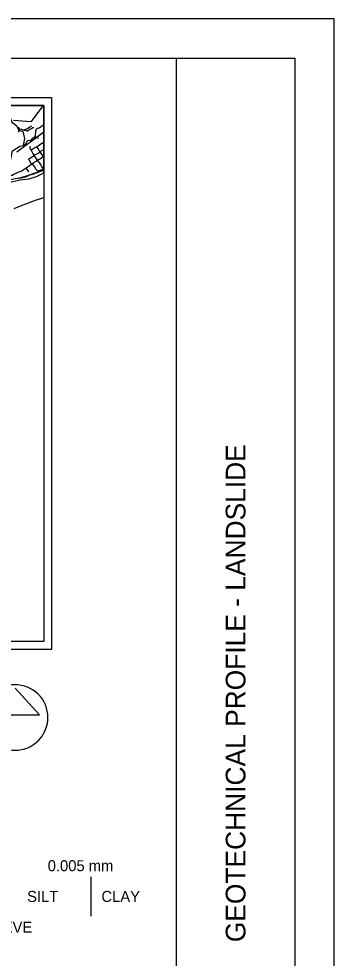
# Model space of a CAD drawing. Extents: x 0 to 34, y 0 to 22.
# Drawn here: x 30 to 34, y 10.08 to 22 of the extents above; entities that cross this region are included whole.
import ezdxf

# ---------------------------------------------------------------- set-up
doc = ezdxf.new("R2010")
doc.units = 0
for name, color, linetype in [('Default', 7, 'Continuous'), ('GM_X_City_Street', 7, 'Continuous'), ('GM_X_County_Road', 7, 'Continuous'), ('GM_X_Major_River', 7, 'Continuous'), ('GM_X_Minor_River', 7, 'Continuous'), ('GM_X_Rail_Line', 7, 'Continuous'), ('GM_X_Section_Text', 7, 'Continuous'), ('GM_X_State_Route', 7, 'Continuous'), ('SH_Border', 7, 'Continuous'), ('SH_Cut_Line', 7, 'Continuous'), ('SH_Data', 7, 'Continuous'), ('SH_Text', 7, 'Continuous')]:
    doc.layers.add(name, color=color, linetype=linetype)

msp = doc.modelspace()

# ---------------------------------------------------------------- linework, layer by layer
at = {"layer": 'Default'}
for points in [[(29.876, 19.923), (30.013, 19.958), (30.128, 19.97), (30.226, 20), (30.317, 20.045), (30.317, 20.9), (27.72, 20.9)], [(29.996, 19.977), (30.019, 19.981), (30.034, 19.983), (30.048, 19.987), (30.071, 19.992), (30.086, 19.995), (30.095, 19.998), (30.108, 20.005), (30.12, 20.011), (30.13, 20.016), (30.147, 20.02), (30.161, 20.025), (30.174, 20.029), (30.193, 20.035), (30.206, 20.04), (30.223, 20.045), (30.239, 20.05), (30.256, 20.057), (30.27, 20.062), (30.283, 20.069), (30.291, 20.072), (30.308, 20.078), (30.317, 20.081), (30.317, 20.9), (29.82, 20.9)], [(29.876, 19.923), (30.013, 19.958), (30.128, 19.97), (30.226, 20), (30.317, 20.045), (30.317, 20.9), (30.309, 20.9), (30.154, 20.693), (29.933, 20.71)]]:
    msp.add_lwpolyline(points, dxfattribs=at)
at = {"layer": 'GM_X_City_Street'}
for points in [[(30.005, 20.606), (30.008, 20.606), (30.01, 20.606), (30.013, 20.606), (30.016, 20.605), (30.032, 20.6), (30.036, 20.599), (30.041, 20.597), (30.046, 20.596), (30.05, 20.595), (30.056, 20.593), (30.07, 20.59), (30.073, 20.589), (30.079, 20.588), (30.096, 20.583), (30.104, 20.581), (30.108, 20.58), (30.111, 20.58), (30.114, 20.58), (30.117, 20.581), (30.119, 20.582), (30.122, 20.583), (30.129, 20.588), (30.134, 20.592), (30.139, 20.596), (30.143, 20.598), (30.156, 20.606), (30.167, 20.613), (30.174, 20.617), (30.179, 20.619), (30.183, 20.621), (30.186, 20.622), (30.188, 20.622), (30.193, 20.622)], [(30.07, 20.59), (30.073, 20.592), (30.074, 20.593), (30.075, 20.594), (30.077, 20.595), (30.08, 20.596), (30.084, 20.597), (30.092, 20.6), (30.099, 20.602), (30.104, 20.605), (30.111, 20.607), (30.116, 20.611), (30.139, 20.625), (30.154, 20.635), (30.159, 20.639), (30.165, 20.642)], [(30.158, 20.333), (30.154, 20.34), (30.151, 20.346), (30.148, 20.352), (30.147, 20.354), (30.146, 20.355), (30.146, 20.356), (30.146, 20.358), (30.145, 20.36), (30.145, 20.362), (30.145, 20.364), (30.145, 20.366), (30.145, 20.369), (30.146, 20.373), (30.147, 20.377), (30.149, 20.385)], [(30.158, 20.333), (30.16, 20.336), (30.162, 20.338), (30.163, 20.339), (30.165, 20.341), (30.17, 20.344), (30.18, 20.351), (30.192, 20.358), (30.218, 20.373), (30.23, 20.38), (30.246, 20.39), (30.264, 20.402), (30.294, 20.421), (30.305, 20.427), (30.309, 20.43), (30.316, 20.435), (30.317, 20.435)], [(30.31, 20.252), (30.305, 20.261), (30.29, 20.286), (30.275, 20.31), (30.272, 20.314), (30.261, 20.331), (30.245, 20.356), (30.239, 20.367), (30.23, 20.38)], [(30.317, 20.408), (30.31, 20.419), (30.305, 20.427)], [(30.13, 20.22), (30.131, 20.222), (30.132, 20.224), (30.133, 20.226), (30.135, 20.228), (30.136, 20.229), (30.138, 20.231), (30.141, 20.233), (30.162, 20.246), (30.17, 20.251), (30.186, 20.261), (30.198, 20.268), (30.222, 20.283), (30.246, 20.297), (30.272, 20.314), (30.285, 20.323), (30.317, 20.342)], [(30.311, 20.099), (30.311, 20.1), (30.311, 20.102), (30.31, 20.103), (30.31, 20.104), (30.308, 20.107), (30.304, 20.114), (30.295, 20.127), (30.276, 20.154), (30.262, 20.175), (30.257, 20.183), (30.251, 20.191), (30.242, 20.202), (30.239, 20.207), (30.235, 20.212), (30.226, 20.224), (30.211, 20.248), (30.198, 20.268), (30.188, 20.284), (30.181, 20.296), (30.161, 20.328), (30.158, 20.333)], [(30.163, 20.157), (30.158, 20.166), (30.136, 20.203), (30.133, 20.207), (30.132, 20.212), (30.131, 20.215), (30.13, 20.217), (30.13, 20.218), (30.13, 20.219), (30.13, 20.22)], [(30.239, 20.07), (30.237, 20.071), (30.236, 20.072), (30.235, 20.073), (30.233, 20.075), (30.223, 20.09), (30.199, 20.126), (30.187, 20.143), (30.178, 20.157), (30.174, 20.164)], [(30.129, 20.058), (30.119, 20.072), (30.112, 20.084), (30.104, 20.095), (30.1, 20.1), (30.095, 20.109)], [(30.239, 20.07), (30.243, 20.07), (30.247, 20.071), (30.255, 20.074), (30.272, 20.08), (30.282, 20.084), (30.302, 20.09), (30.305, 20.091), (30.307, 20.093), (30.308, 20.094), (30.309, 20.096), (30.31, 20.097), (30.311, 20.099)]]:
    msp.add_lwpolyline(points, dxfattribs=at)
at = {"layer": 'GM_X_County_Road'}
msp.add_lwpolyline([(30.001, 20.563), (30.002, 20.572), (30.003, 20.58), (30.004, 20.588), (30.005, 20.598), (30.005, 20.6), (30.006, 20.603), (30.005, 20.606), (30.005, 20.608), (30.005, 20.613), (30.004, 20.617), (30.002, 20.622), (30.001, 20.626)], dxfattribs=at)
at = {"layer": 'GM_X_Major_River'}
for points in [[(30.317, 20.079), (30.302, 20.073), (30.278, 20.065), (30.097, 20.004), (30.023, 19.982), (29.898, 19.958), (29.832, 19.942)], [(29.941, 19.593), (30.045, 19.637), (30.105, 19.657), (30.18, 19.688), (30.239, 19.707), (30.282, 19.722), (30.317, 19.731)]]:
    msp.add_lwpolyline(points, dxfattribs=at)
at = {"layer": 'GM_X_Minor_River'}
for points in [[(29.863, 20.103), (29.85, 20.186), (29.888, 20.195), (29.902, 20.221), (29.922, 20.326), (30.015, 20.384), (30.061, 20.392), (30.077, 20.483), (30.066, 20.537), (30.056, 20.564), (30.007, 20.581), (29.978, 20.639), (29.927, 20.676), (29.912, 20.699), (29.895, 20.738), (29.892, 20.876), (29.896, 20.9)], [(30.061, 20.392), (30.093, 20.416), (30.111, 20.454), (30.127, 20.459), (30.142, 20.455), (30.154, 20.456), (30.178, 20.485), (30.197, 20.499), (30.213, 20.513), (30.217, 20.58), (30.228, 20.605), (30.238, 20.614), (30.26, 20.617), (30.317, 20.661)]]:
    msp.add_lwpolyline(points, dxfattribs=at)
at = {"layer": 'GM_X_Rail_Line'}
msp.add_lwpolyline([(29.976, 20.314), (30.027, 20.351), (30.149, 20.441), (30.317, 20.565)], dxfattribs=at)
at = {"layer": 'GM_X_State_Route'}
msp.add_lwpolyline([(29.9, 20.01), (29.905, 20.012), (29.914, 20.016), (29.919, 20.018), (29.938, 20.027), (29.986, 20.049), (29.995, 20.053), (30.018, 20.063), (30.039, 20.073), (30.055, 20.082), (30.07, 20.092), (30.091, 20.106), (30.095, 20.109), (30.163, 20.156), (30.163, 20.157), (30.174, 20.164), (30.194, 20.178), (30.222, 20.196), (30.239, 20.207), (30.288, 20.238), (30.31, 20.252), (30.317, 20.256)], dxfattribs=at)
at = {"layer": 'SH_Border'}
msp.add_line((32, 0.5), (32, 21.5), dxfattribs=at)
msp.add_lwpolyline([(1.5, 21.5), (33.5, 21.5), (33.5, 0.5), (1.5, 0.5)], close=True, dxfattribs=at)
at = {"layer": 'SH_Cut_Line'}
msp.add_lwpolyline([(0, 0), (34, 0), (34, 22), (0, 22)], close=True, dxfattribs=at)
at = {"layer": 'SH_Data'}
for p, q in [((30.264, 13.17), (29.956, 13.511)), ((29.648, 13.17), (30.264, 13.17)), ((30.919, 10.617), (30.919, 11.117))]:
    msp.add_line(p, q, dxfattribs=at)
for points in [[(23.417, 21), (30.417, 21), (30.417, 14), (23.417, 14)], [(23.517, 20.9), (30.317, 20.9), (30.317, 14.1), (23.517, 14.1)]]:
    msp.add_lwpolyline(points, close=True, dxfattribs=at)
msp.add_arc((29.956, 13.137), 0.415, 129.7798, 129.7633, dxfattribs=at)
at = {"layer": 'SH_Text'}
msp.add_lwpolyline([(29.876, 19.923), (30.013, 19.958), (30.128, 19.97), (30.226, 20), (30.317, 20.045), (30.317, 20.9), (23.517, 20.9)], dxfattribs=at)

# ---------------------------------------------------------------- texts
at = {"layer": 'GM_X_Section_Text'}
msp.add_text('23', height=0.0419, rotation=0, dxfattribs=at).set_placement((30.194, 20.474))
at = {"layer": 'SH_Data'}
msp.add_text('GEOTECHNICAL PROFILE - LANDSLIDE', height=0.25, rotation=90, dxfattribs=at).set_placement((32.875, 10.287))
at = {"layer": 'SH_Text'}
for s, p in [('0.005 mm', (30.368, 11.187)), ('SILT', (30.107, 10.797)), ('CLAY', (31.049, 10.797)), ('No. 200 SIEVE', (28.913, 10.407))]:
    msp.add_text(s, height=0.14, dxfattribs=at).set_placement(p)

doc.saveas('drawing.dxf')
